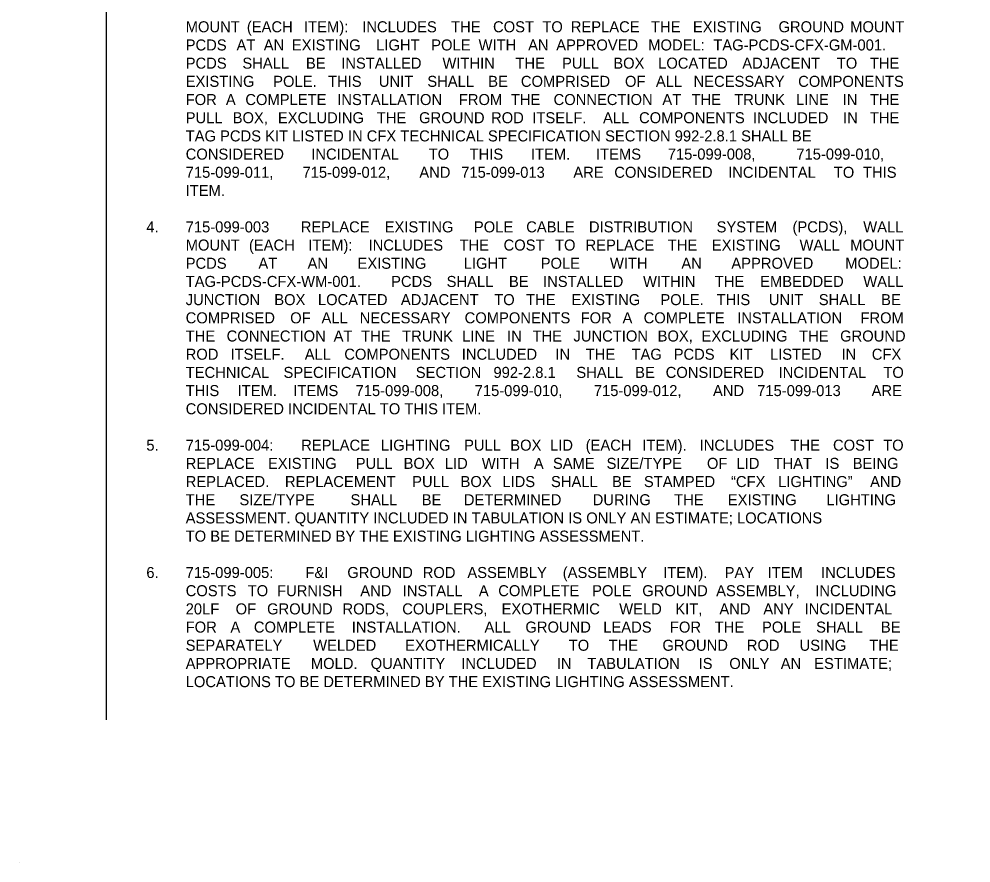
# Model space of a CAD drawing. Extents: x -55 to 2471539, y -90 to 3608906.
# Drawn here: x -55 to 543, y -90 to 440 of the extents above; entities that cross this region are included whole.
import ezdxf

# ---------------------------------------------------------------- set-up
doc = ezdxf.new("R2010")
doc.units = 0
for name, color, linetype in [('AdhocPoint_dp', 7, 'Continuous'), ('NonPlottingEle_dp', 7, 'Continuous'), ('TextNotes', 7, 'Continuous')]:
    doc.layers.add(name, color=color, linetype=linetype)

msp = doc.modelspace()

# ---------------------------------------------------------------- linework, layer by layer
at = {"layer": 'AdhocPoint_dp'}
msp.add_line((-55, -90), (-55, -90), dxfattribs=at)
at = {"layer": 'NonPlottingEle_dp'}
msp.add_lwpolyline([(0, 0), (0, 960), (1540, 960), (1540, 0)], dxfattribs=at)

# ---------------------------------------------------------------- texts
at = {"layer": 'TextNotes'}
for s, p in [('MOUNT ', (49.75, 432.14)), ('(EACH ', (88.2, 432.14)), ('ITEM): ', (124.16, 432.14)), ('INCLUDES ', (160.72, 432.14)), ('THE ', (216.58, 432.14)), ('COST ', (242.95, 432.14)), ('TO ', (273.95, 432.14)), ('REPLACE ', (291.81, 432.14)), ('THE ', (342.23, 432.14)), ('EXISTING ', (368.6, 432.14)), ('GROUND ', (422.37, 432.14)), ('MOUNT ', (467.44, 432.14)), ('PCDS ', (49.75, 420.71)), ('AT ', (81.71, 420.71)), ('AN ', (98.83, 420.71)), ('EXISTING ', (116.5, 420.71)), ('LIGHT ', (169.49, 420.71)), ('POLE ', (204.09, 420.71)), ('WITH ', (233.86, 420.71)), ('AN ', (265, 420.71)), ('APPROVED ', (282.66, 420.71)), ('MODEL: ', (340.5, 420.71)), ('TAG-PCDS-CFX-GM-001. ', (381.42, 420.71)), ('PCDS ', (49.75, 409.27)), ('SHALL ', (85.39, 409.27)), ('BE ', (125.34, 409.27)), ('INSTALLED ', (147.52, 409.27)), ('WITHIN ', (211.16, 409.27)), ('THE ', (257.02, 409.27)), ('PULL ', (286.29, 409.27)), ('BOX ', (318.54, 409.27)), ('LOCATED ', (346.74, 409.27)), ('ADJACENT ', (399.62, 409.27)), ('TO ', (459.04, 409.27)), ('THE ', (479.8, 409.27)), ('EXISTING ', (49.75, 397.84)), ('POLE. ', (104.76, 397.84)), ('THIS ', (139.22, 397.84)), ('UNIT ', (171.15, 397.84)), ('SHALL ', (201.63, 397.84)), ('BE ', (239.92, 397.84)), ('COMPRISED ', (260.45, 397.84)), ('OF ', (325.88, 397.84)), ('ALL ', (345.31, 397.84)), ('NECESSARY ', (369.01, 397.84)), ('COMPONENTS ', (434.75, 397.84)), ('FOR ', (49.75, 386.4)), ('A ', (75.02, 386.4)), ('COMPLETE ', (87.25, 386.4)), ('INSTALLATION ', (145.03, 386.4)), ('FROM ', (221.45, 386.4)), ('THE ', (254.17, 386.4)), ('CONNECTION ', (281, 386.4)), ('AT ', (349.37, 386.4)), ('THE ', (367.73, 386.4)), ('TRUNK ', (394.56, 386.4)), ('LINE ', (433.4, 386.4)), ('IN ', (462.71, 386.4)), ('THE ', (479.8, 386.4)), ('PULL ', (49.75, 374.97)), ('BOX, ', (79.29, 374.97)), ('EXCLUDING ', (107.73, 374.97)), ('THE ', (169.89, 374.97)), ('GROUND ', (196.46, 374.97)), ('ROD ', (241.71, 374.97)), ('ITSELF. ', (267.65, 374.97)), ('ALL ', (312.1, 374.97)), ('COMPONENTS ', (334.74, 374.97)), ('INCLUDED ', (406.35, 374.97)), ('IN ', (462.98, 374.97)), ('THE ', (479.8, 374.97)), ('TAG PCDS KIT LISTED IN CFX TECHNICAL SPECIFICATION SECTION 992-2.8.1 SHALL BE ', (49.75, 363.54)), ('CONSIDERED ', (49.75, 352.1)), ('INCIDENTAL ', (128.7, 352.1)), ('TO ', (202.5, 352.1)), ('THIS ', (228.22, 352.1)), ('ITEM. ', (266.76, 352.1)), ('ITEMS ', (307.69, 352.1)), ('715-099-008, ', (352.78, 352.1)), ('715-099-010, ', (433.6, 352.1)), ('715-099-011, ', (49.75, 340.67)), ('715-099-012, ', (123.18, 340.67)), ('AND ', (196.62, 340.67)), ('715-099-013 ', (222.94, 340.67)), ('ARE ', (293.43, 340.67)), ('CONSIDERED ', (319.17, 340.67)), ('INCIDENTAL ', (390.73, 340.67)), ('TO ', (457.15, 340.67)), ('THIS ', (475.49, 340.67)), ('ITEM.', (49.75, 329.23)), ('4.', (25.02, 306.36)), ('715-099-003 ', (49.75, 306.36)), ('REPLACE ', (122.08, 306.36)), ('EXISTING ', (174.82, 306.36)), ('POLE ', (230.91, 306.36)), ('CABLE ', (263.79, 306.36)), ('DISTRIBUTION ', (303.24, 306.36)), ('SYSTEM ', (383.47, 306.36)), ('(PCDS), ', (431.19, 306.36)), ('WALL ', (475.67, 306.36)), ('MOUNT ', (49.75, 294.93)), ('(EACH ', (89.52, 294.93)), ('ITEM): ', (126.81, 294.93)), ('INCLUDES ', (164.7, 294.93)), ('THE ', (221.87, 294.93)), ('COST ', (249.57, 294.93)), ('TO ', (281.9, 294.93)), ('REPLACE ', (301.08, 294.93)), ('THE ', (352.82, 294.93)), ('EXISTING ', (380.52, 294.93)), ('WALL ', (435.62, 294.93)), ('MOUNT ', (467.44, 294.93)), ('PCDS ', (49.75, 283.49)), ('AT ', (95.47, 283.49)), ('AN ', (126.36, 283.49)), ('EXISTING ', (157.78, 283.49)), ('LIGHT ', (224.53, 283.49)), ('POLE ', (272.9, 283.49)), ('WITH ', (316.43, 283.49)), ('AN ', (361.33, 283.49)), ('APPROVED ', (392.75, 283.49)), ('MODEL: ', (464.35, 283.49)), ('TAG-PCDS-CFX-WM-001. ', (49.75, 272.06)), ('PCDS ', (178.89, 272.06)), ('SHALL ', (213.77, 272.06)), ('BE ', (252.95, 272.06)), ('INSTALLED ', (274.37, 272.06)), ('WITHIN ', (337.24, 272.06)), ('THE ', (382.34, 272.06)), ('EMBEDDED ', (410.85, 272.06)), ('WALL ', (475.67, 272.06)), ('JUNCTION ', (49.75, 260.63)), ('BOX ', (105.43, 260.63)), ('LOCATED ', (132.88, 260.63)), ('ADJACENT ', (185, 260.63)), ('TO ', (243.68, 260.63)), ('THE ', (263.68, 260.63)), ('EXISTING ', (292.21, 260.63)), ('POLE. ', (348.13, 260.63)), ('THIS ', (383.49, 260.63)), ('UNIT ', (416.32, 260.63)), ('SHALL ', (447.7, 260.63)), ('BE ', (486.9, 260.63)), ('COMPRISED ', (49.75, 249.19)), ('OF ', (115.44, 249.19)), ('ALL ', (135.14, 249.19)), ('NECESSARY ', (159.1, 249.19)), ('COMPONENTS ', (225.09, 249.19)), ('FOR ', (298.02, 249.19)), ('A ', (324.35, 249.19)), ('COMPLETE ', (337.61, 249.19)), ('INSTALLATION ', (396.45, 249.19)), ('FROM ', (473.91, 249.19)), ('THE ', (49.75, 237.76)), ('CONNECTION ', (75.49, 237.76)), ('AT ', (142.77, 237.76)), ('THE ', (160.05, 237.76)), ('TRUNK ', (185.79, 237.76)), ('LINE ', (223.54, 237.76)), ('IN ', (251.76, 237.76)), ('THE ', (267.76, 237.76)), ('JUNCTION ', (293.51, 237.76)), ('BOX, ', (346.4, 237.76)), ('EXCLUDING ', (374.02, 237.76)), ('THE ', (435.36, 237.76)), ('GROUND ', (461.11, 237.76)), ('ROD ', (49.75, 226.32)), ('ITSELF. ', (77.92, 226.32)), ('ALL ', (124.59, 226.32)), ('COMPONENTS ', (149.46, 226.32)), ('INCLUDED ', (223.3, 226.32)), ('IN ', (282.15, 226.32)), ('THE ', (301.2, 226.32)), ('TAG ', (329.99, 226.32)), ('PCDS ', (356.48, 226.32)), ('KIT ', (391.64, 226.32)), ('LISTED ', (417.04, 226.32)), ('IN ', (461.99, 226.32)), ('CFX ', (481.03, 226.32)), ('TECHNICAL ', (49.75, 214.89)), ('SPECIFICATION ', (111.24, 214.89)), ('SECTION ', (194.38, 214.89)), ('992-2.8.1 ', (243.21, 214.89)), ('SHALL ', (295.31, 214.89)), ('BE ', (332.27, 214.89)), ('CONSIDERED ', (351.46, 214.89)), ('INCIDENTAL ', (422.46, 214.89)), ('TO ', (488.31, 214.89)), ('THIS ', (49.75, 203.45)), ('ITEM. ', (82.37, 203.45)), ('ITEMS ', (117.37, 203.45)), ('715-099-008, ', (156.53, 203.45)), ('715-099-010, ', (231.42, 203.45)), ('715-099-012, ', (306.31, 203.45)), ('AND ', (381.19, 203.45)), ('715-099-013 ', (408.98, 203.45)), ('ARE ', (480.91, 203.45)), ('CONSIDERED INCIDENTAL TO THIS ITEM.', (49.75, 192.02)), ('5.', (25.02, 169.15)), ('715-099-004: ', (49.75, 169.15)), ('REPLACE ', (122.36, 169.15)), ('LIGHTING ', (172.46, 169.15)), ('PULL ', (224.76, 169.15)), ('BOX ', (253.79, 169.15)), ('LID ', (278.78, 169.15)), ('(EACH ', (301.17, 169.15)), ('ITEM). ', (336.82, 169.15)), ('INCLUDES ', (372.81, 169.15)), ('THE ', (429.88, 169.15)), ('COST ', (456.65, 169.15)), ('TO ', (488.18, 169.15)), ('REPLACE ', (49.75, 157.71)), ('EXISTING ', (101.47, 157.71)), ('PULL ', (156.65, 157.71)), ('BOX ', (186.72, 157.71)), ('LID ', (212.64, 157.71)), ('WITH ', (235.88, 157.71)), ('A ', (268.59, 157.71)), ('SAME ', (280.6, 157.71)), ('SIZE/TYPE ', (314.32, 157.71)), ('OF ', (377.41, 157.71)), ('LID ', (396.02, 157.71)), ('THAT ', (419.26, 157.71)), ('IS ', (451.88, 157.71)), ('BEING ', (469.03, 157.71)), ('REPLACED. ', (49.75, 146.28)), ('REPLACEMENT ', (112.15, 146.28)), ('PULL ', (192.11, 146.28)), ('BOX ', (222.53, 146.28)), ('LIDS ', (248.79, 146.28)), ('SHALL ', (279.38, 146.28)), ('BE ', (317.71, 146.28)), ('STAMPED ', (337.78, 146.28)), ('“CFX ', (392.56, 146.28)), ('LIGHTING” ', (422.15, 146.28)), ('AND ', (479.97, 146.28)), ('THE ', (49.75, 134.85)), ('SIZE/TYPE ', (83.53, 134.85)), ('SHALL ', (153.39, 134.85)), ('BE ', (198.14, 134.85)), ('DETERMINED ', (224.63, 134.85)), ('DURING ', (305.58, 134.85)), ('THE ', (356.76, 134.85)), ('EXISTING ', (390.54, 134.85)), ('LIGHTING ', (452.48, 134.85)), ('ASSESSMENT. QUANTITY INCLUDED IN TABULATION IS ONLY AN ESTIMATE; LOCATIONS ', (49.75, 123.41)), ('TO BE DETERMINED BY THE EXISTING LIGHTING ASSESSMENT.', (49.75, 111.98)), ('6.', (25.02, 89.11)), ('715-099-005: ', (49.75, 89.11)), ('F&I ', (125, 89.11)), ('GROUND ', (151.36, 89.11)), ('ROD ', (198.75, 89.11)), ('ASSEMBLY ', (226.82, 89.11)), ('(ASSEMBLY ', (286.75, 89.11)), ('ITEM). ', (349.9, 89.11)), ('PAY ', (388.52, 89.11)), ('ITEM ', (415.58, 89.11)), ('INCLUDES ', (449.13, 89.11)), ('COSTS ', (49.75, 77.67)), ('TO ', (88.73, 77.67)), ('FURNISH ', (107.19, 77.67)), ('AND ', (159.49, 77.67)), ('INSTALL ', (186.17, 77.67)), ('A ', (234.02, 77.67)), ('COMPLETE ', (246.22, 77.67)), ('POLE ', (305.25, 77.67)), ('GROUND ', (336.75, 77.67)), ('ASSEMBLY, ', (383.18, 77.67)), ('INCLUDING ', (445.51, 77.67)), ('20LF ', (49.75, 66.24)), ('OF ', (81.15, 66.24)), ('GROUND ', (100.92, 66.24)), ('RODS, ', (148.3, 66.24)), ('COUPLERS, ', (185.88, 66.24)), ('EXOTHERMIC ', (248.33, 66.24)), ('WELD ', (322.26, 66.24)), ('KIT, ', (357.51, 66.24)), ('AND ', (385.23, 66.24)), ('ANY ', (412.86, 66.24)), ('INCIDENTAL ', (438.77, 66.24)), ('FOR ', (49.75, 54.8)), ('A ', (77.88, 54.8)), ('COMPLETE ', (92.61, 54.8)), ('INSTALLATION. ', (154.15, 54.8)), ('ALL ', (237.58, 54.8)), ('GROUND ', (263.29, 54.8)), ('LEADS ', (312.24, 54.8)), ('FOR ', (354.13, 54.8)), ('THE ', (382.27, 54.8)), ('POLE ', (412, 54.8)), ('SHALL ', (446.03, 54.8)), ('BE ', (486.73, 54.8)), ('SEPARATELY ', (49.75, 43.37)), (' WELDED ', (127.32, 43.37)), ('EXOTHERMICALLY ', (187.75, 43.37)), ('TO ', (290.53, 43.37)), ('THE ', (315.61, 43.37)), ('GROUND ', (349.42, 43.37)), ('ROD ', (402.46, 43.37)), ('USING ', (435.64, 43.37)), ('THE ', (479.44, 43.37)), ('APPROPRIATE ', (49.75, 31.94)), ('MOLD. ', (128.43, 31.94)), ('QUANTITY ', (166.03, 31.94)), ('INCLUDED ', (222.99, 31.94)), ('IN ', (283.06, 31.94)), ('TABULATION ', (302.22, 31.94)), ('IS ', (372.16, 31.94)), ('ONLY ', (391.46, 31.94)), ('AN ', (423.81, 31.94)), ('ESTIMATE; ', (444.84, 31.94)), ('LOCATIONS TO BE DETERMINED BY THE EXISTING LIGHTING ASSESSMENT.', (49.75, 20.5))]:
    msp.add_text(s, height=6.93, dxfattribs=at).set_placement(p)

doc.saveas('drawing.dxf')
